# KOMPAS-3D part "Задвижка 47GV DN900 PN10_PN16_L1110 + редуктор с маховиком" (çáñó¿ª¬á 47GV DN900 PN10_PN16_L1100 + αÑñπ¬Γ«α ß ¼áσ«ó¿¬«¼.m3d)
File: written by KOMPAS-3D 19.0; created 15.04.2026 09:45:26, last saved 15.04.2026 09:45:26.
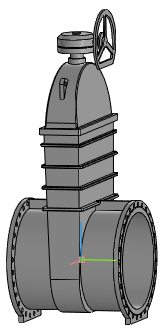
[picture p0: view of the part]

Document properties: Автор: Энергия; Полное имя файла: ..\..\Задвижка 47GV DN800 PN10_PN16_L1100 + редуктор с маховиком.a3d

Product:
- Part/product: Задвижка 47GV DN900 PN10_PN16_L1110 + редуктор с маховиком
    Масса: 4527.48

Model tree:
1. Операция без истории:1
